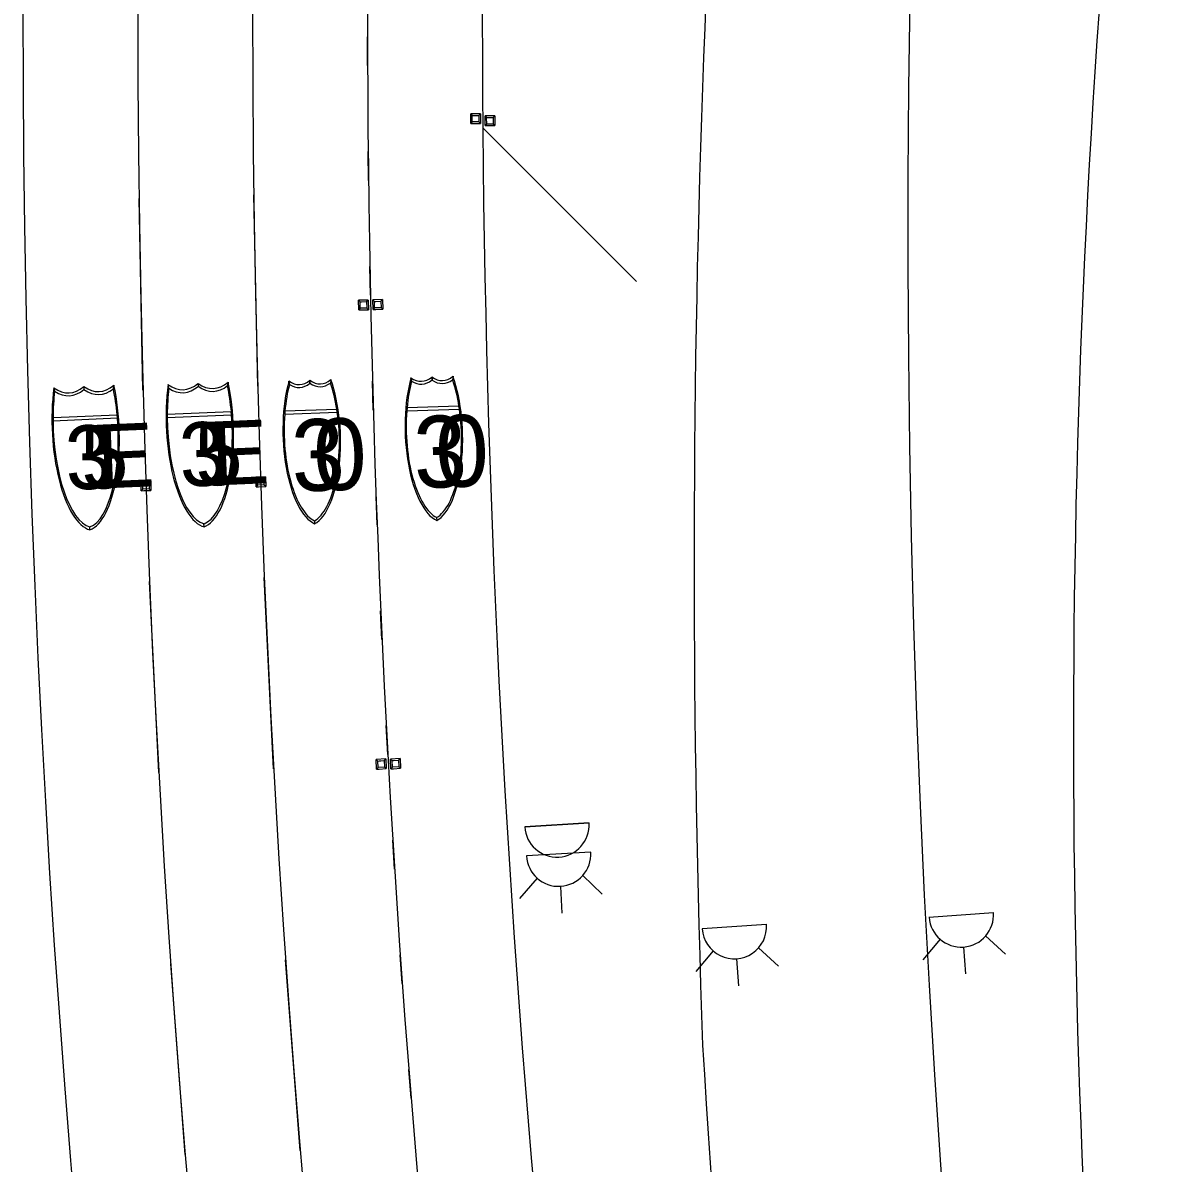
# Model space of a CAD drawing. Extents: x 2471014 to 2497726, y 6959577 to 6980268.
# Drawn here: x 2488424.4 to 2488544.1, y 6963415.2 to 6963534.3 of the extents above; entities that cross this region are included whole.
import ezdxf

# ---------------------------------------------------------------- set-up
doc = ezdxf.new("R2010")
doc.units = 0
for name, color, linetype in [('13', 7, 'Continuous'), ('18', 7, 'Continuous'), ('23', 7, 'Continuous'), ('59', 7, 'Continuous'), ('C-COMM-IDEN', 7, 'Continuous'), ('G-GRID-MAJR', 7, 'Continuous'), ('Level 30', 7, 'Continuous'), ('Level 40', 7, 'Continuous'), ('PMK_Del_D-SY_SZ_TYC_CTB', 7, 'Continuous'), ('PMK_Pav_Mark_Multi_Shield', 7, 'Continuous'), ('RDWY_PAVE_XSTREET_FOC', 7, 'Continuous'), ('V7_25', 7, 'Continuous')]:
    doc.layers.add(name, color=color, linetype=linetype)

msp = doc.modelspace()

# ---------------------------------------------------------------- linework, layer by layer
at = {"layer": '13'}
for centre, radius, start, end in [((2489874.44, 6963535.43), 1450, 149.83805, 187.72757), ((2489908.57, 6963477.79), 1414, 165.82987, 182.03801), ((2489609.21, 6963459.85), 1075, 166.29175, 188.37964), ((2489916.91, 6963512.7), 1424, 183.42984, 191.359)]:
    msp.add_arc(centre, radius, start, end, dxfattribs=at)
at = {"layer": '18'}
for centre, radius, start, end in [((2489916.91, 6963512.7), 1400, 142.23979, 191.359), ((2489874.44, 6963535.43), 1402, 167.63271, 187.72757)]:
    msp.add_arc(centre, radius, start, end, dxfattribs=at)
at = {"layer": '23'}
for p, q in [((2488471.24, 6963523.78), (2488471.23, 6963524.8)), ((2488472.24, 6963524.8), (2488471.23, 6963524.8)), ((2488471.23, 6963524.8), (2488471.39, 6963524.63)), ((2488472.07, 6963524.63), (2488472.24, 6963524.8)), ((2488472.24, 6963524.8), (2488472.25, 6963523.79)), ((2488471.4, 6963523.95), (2488471.24, 6963523.78)), ((2488471.24, 6963523.78), (2488471.51, 6963523.79)), ((2488471.39, 6963524.63), (2488471.53, 6963524.63)), ((2488472.07, 6963523.96), (2488471.4, 6963523.95)), ((2488471.51, 6963523.79), (2488472.25, 6963523.79)), ((2488471.53, 6963524.63), (2488472.07, 6963524.63)), ((2488472.25, 6963523.79), (2488472.07, 6963523.96)), ((2488473.74, 6963524.58), (2488472.73, 6963524.57)), ((2488472.74, 6963523.56), (2488472.73, 6963524.57)), ((2488472.73, 6963524.57), (2488472.89, 6963524.4)), ((2488472.9, 6963523.73), (2488472.74, 6963523.56)), ((2488472.89, 6963524.4), (2488473.03, 6963524.41)), ((2488473.57, 6963523.73), (2488472.9, 6963523.73)), ((2488473.03, 6963524.41), (2488473.57, 6963524.41)), ((2488473.57, 6963524.41), (2488473.74, 6963524.58)), ((2488473.75, 6963523.57), (2488473.57, 6963523.73)), ((2488473.74, 6963524.58), (2488473.75, 6963523.57)), ((2488472.74, 6963523.56), (2488473.01, 6963523.56)), ((2488473.01, 6963523.56), (2488473.75, 6963523.57)), ((2488460.52, 6963505.34), (2488459.51, 6963505.32)), ((2488459.53, 6963504.31), (2488459.51, 6963505.32)), ((2488459.51, 6963505.32), (2488459.67, 6963505.16)), ((2488459.69, 6963504.48), (2488459.53, 6963504.31)), ((2488459.67, 6963505.16), (2488459.81, 6963505.16)), ((2488460.36, 6963504.49), (2488459.69, 6963504.48)), ((2488459.81, 6963505.16), (2488460.35, 6963505.17)), ((2488460.35, 6963505.17), (2488460.52, 6963505.34)), ((2488460.55, 6963504.33), (2488460.36, 6963504.49)), ((2488460.52, 6963505.34), (2488460.55, 6963504.33)), ((2488462.02, 6963505.38), (2488461.01, 6963505.36)), ((2488461.03, 6963504.35), (2488461.01, 6963505.36)), ((2488461.01, 6963505.36), (2488461.17, 6963505.19)), ((2488461.19, 6963504.52), (2488461.03, 6963504.35)), ((2488461.17, 6963505.19), (2488461.31, 6963505.2)), ((2488461.86, 6963504.53), (2488461.19, 6963504.52)), ((2488461.31, 6963505.2), (2488461.85, 6963505.21)), ((2488461.85, 6963505.21), (2488462.02, 6963505.38)), ((2488462.04, 6963504.37), (2488461.86, 6963504.53)), ((2488462.02, 6963505.38), (2488462.04, 6963504.37)), ((2488459.53, 6963504.31), (2488459.8, 6963504.31)), ((2488459.8, 6963504.31), (2488460.55, 6963504.33)), ((2488461.03, 6963504.35), (2488461.3, 6963504.35)), ((2488461.3, 6963504.35), (2488462.04, 6963504.37)), ((2488449.78, 6963486.87), (2488448.77, 6963486.84)), ((2488448.8, 6963485.82), (2488448.77, 6963486.84)), ((2488448.77, 6963486.84), (2488448.93, 6963486.67)), ((2488448.93, 6963486.67), (2488449.07, 6963486.68)), ((2488449.07, 6963486.68), (2488449.61, 6963486.7)), ((2488449.61, 6963486.7), (2488449.78, 6963486.87)), ((2488449.78, 6963486.87), (2488449.82, 6963485.86)), ((2488437.79, 6963486.46), (2488436.77, 6963486.43)), ((2488436.81, 6963485.42), (2488436.77, 6963486.43)), ((2488436.77, 6963486.43), (2488436.94, 6963486.27)), ((2488436.96, 6963485.59), (2488436.81, 6963485.42)), ((2488436.81, 6963485.42), (2488437.08, 6963485.43)), ((2488436.94, 6963486.27), (2488437.08, 6963486.27)), ((2488437.64, 6963485.61), (2488436.96, 6963485.59)), ((2488437.08, 6963486.27), (2488437.62, 6963486.29)), ((2488437.08, 6963485.43), (2488437.82, 6963485.45)), ((2488437.62, 6963486.29), (2488437.79, 6963486.46)), ((2488437.82, 6963485.45), (2488437.64, 6963485.61)), ((2488437.79, 6963486.46), (2488437.82, 6963485.45)), ((2488448.96, 6963486), (2488448.8, 6963485.82)), ((2488448.8, 6963485.82), (2488449.07, 6963485.83)), ((2488449.63, 6963486.02), (2488448.96, 6963486)), ((2488449.07, 6963485.83), (2488449.82, 6963485.86)), ((2488449.82, 6963485.86), (2488449.63, 6963486.02)), ((2488462.36, 6963457.4), (2488461.34, 6963457.34)), ((2488461.4, 6963456.33), (2488461.34, 6963457.34)), ((2488461.34, 6963457.34), (2488461.51, 6963457.18)), ((2488461.51, 6963457.18), (2488461.65, 6963457.19)), ((2488461.65, 6963457.19), (2488462.19, 6963457.22)), ((2488462.19, 6963457.22), (2488462.36, 6963457.4)), ((2488462.36, 6963457.4), (2488462.41, 6963456.39)), ((2488463.86, 6963457.44), (2488462.85, 6963457.38)), ((2488462.9, 6963456.37), (2488462.85, 6963457.38)), ((2488462.85, 6963457.38), (2488463.01, 6963457.22)), ((2488463.01, 6963457.22), (2488463.16, 6963457.23)), ((2488463.73, 6963456.58), (2488463.05, 6963456.54)), ((2488463.16, 6963457.23), (2488463.69, 6963457.26)), ((2488463.69, 6963457.26), (2488463.86, 6963457.44)), ((2488463.91, 6963456.42), (2488463.73, 6963456.58)), ((2488463.86, 6963457.44), (2488463.91, 6963456.42)), ((2488461.55, 6963456.51), (2488461.4, 6963456.33)), ((2488461.4, 6963456.33), (2488461.67, 6963456.34)), ((2488462.23, 6963456.54), (2488461.55, 6963456.51)), ((2488461.67, 6963456.34), (2488462.41, 6963456.39)), ((2488462.41, 6963456.39), (2488462.23, 6963456.54)), ((2488463.05, 6963456.54), (2488462.9, 6963456.37)), ((2488462.9, 6963456.37), (2488463.17, 6963456.38)), ((2488463.17, 6963456.38), (2488463.91, 6963456.42))]:
    msp.add_line(p, q, dxfattribs=at)
for points in [[(2488471.4, 6963523.95), (2488471.39, 6963524.63), (2488472.07, 6963524.63), (2488472.07, 6963523.96)], [(2488472.9, 6963523.73), (2488472.89, 6963524.4), (2488473.57, 6963524.41), (2488473.57, 6963523.73)], [(2488459.69, 6963504.48), (2488459.67, 6963505.16), (2488460.35, 6963505.17), (2488460.36, 6963504.49)], [(2488461.19, 6963504.52), (2488461.17, 6963505.19), (2488461.85, 6963505.21), (2488461.86, 6963504.53)], [(2488448.96, 6963486), (2488448.93, 6963486.67), (2488449.61, 6963486.7), (2488449.63, 6963486.02)], [(2488436.96, 6963485.59), (2488436.94, 6963486.27), (2488437.62, 6963486.29), (2488437.64, 6963485.61)], [(2488461.55, 6963456.51), (2488461.51, 6963457.18), (2488462.19, 6963457.22), (2488462.23, 6963456.54)], [(2488463.05, 6963456.54), (2488463.01, 6963457.22), (2488463.69, 6963457.26), (2488463.73, 6963456.58)]]:
    msp.add_lwpolyline(points, close=True, dxfattribs=at)
at = {"layer": '59'}
msp.add_arc((2489874.44, 6963535.43), 1414, 167.6301, 187.72757, dxfattribs=at)
at = {"layer": 'C-COMM-IDEN'}
for p, q in [((2488476.88, 6963450.32), (2488483.61, 6963450.71)), ((2488483.61, 6963450.71), (2488476.88, 6963450.32)), ((2488483.79, 6963447.66), (2488477.05, 6963447.27)), ((2488478.17, 6963444.95), (2488476.33, 6963442.82)), ((2488482.94, 6963445.22), (2488484.96, 6963443.26)), ((2488480.61, 6963444.09), (2488480.77, 6963441.29))]:
    msp.add_line(p, q, dxfattribs=at)
for centre in [(2488480.24, 6963450.51), (2488480.42, 6963447.46)]:
    msp.add_arc(centre, 3.37, 183.2424, 3.2424, dxfattribs=at)
at = {"layer": 'G-GRID-MAJR'}
msp.add_line((2488472.49, 6963523.33), (2488488.54, 6963507.28), dxfattribs=at)
at = {"layer": 'Level 30'}
for p, q in [((2488519.12, 6963440.86), (2488525.85, 6963441.36)), ((2488525.04, 6963438.91), (2488527.1, 6963436.99)), ((2488520.28, 6963438.56), (2488518.47, 6963436.4)), ((2488522.73, 6963437.75), (2488522.94, 6963434.94))]:
    msp.add_line(p, q, dxfattribs=at)
msp.add_arc((2488522.49, 6963441.11), 3.37, 184.2283, 4.2282, dxfattribs=at)
at = {"layer": 'Level 40'}
for p, q in [((2488460.45, 6963529.84), (2488460.44, 6963532.84)), ((2488460.55, 6963517.84), (2488460.51, 6963520.84)), ((2488460.75, 6963505.84), (2488460.69, 6963508.84)), ((2488461.05, 6963493.85), (2488460.96, 6963496.85)), ((2488461.45, 6963481.86), (2488461.34, 6963484.85)), ((2488461.96, 6963469.87), (2488461.82, 6963472.86)), ((2488462.56, 6963457.88), (2488462.4, 6963460.88)), ((2488463.27, 6963445.9), (2488463.09, 6963448.9)), ((2488464.08, 6963433.93), (2488463.87, 6963436.92)), ((2488465, 6963421.96), (2488464.76, 6963424.96))]:
    msp.add_line(p, q, dxfattribs=at)
at = {"layer": 'PMK_Del_D-SY_SZ_TYC_CTB'}
for p, q in [((2488502.14, 6963440.12), (2488495.41, 6963439.65)), ((2488501.32, 6963437.67), (2488503.38, 6963435.75)), ((2488496.56, 6963437.34), (2488494.75, 6963435.19)), ((2488499.01, 6963436.52), (2488499.21, 6963433.71))]:
    msp.add_line(p, q, dxfattribs=at)
msp.add_arc((2488498.78, 6963439.89), 3.37, 184.033, 4.033, dxfattribs=at)
at = {"layer": 'PMK_Pav_Mark_Multi_Shield'}
for p, q in [((2488467.19, 6963497.3), (2488467.2, 6963496.99)), ((2488467.2, 6963496.99), (2488467.19, 6963497.3)), ((2488469.38, 6963497.37), (2488469.34, 6963497.01)), ((2488469.38, 6963497.37), (2488469.34, 6963497.01)), ((2488427.76, 6963495.81), (2488427.67, 6963496.18)), ((2488427.76, 6963495.81), (2488427.67, 6963496.18)), ((2488430.81, 6963496.31), (2488430.82, 6963496)), ((2488433.89, 6963496.07), (2488433.94, 6963496.44)), ((2488433.94, 6963496.44), (2488433.89, 6963496.07)), ((2488439.68, 6963496.13), (2488439.6, 6963496.5)), ((2488439.68, 6963496.13), (2488439.6, 6963496.5)), ((2488442.73, 6963496.63), (2488442.75, 6963496.32)), ((2488445.82, 6963496.39), (2488445.87, 6963496.77)), ((2488445.87, 6963496.77), (2488445.82, 6963496.39)), ((2488452.29, 6963496.52), (2488452.23, 6963496.88)), ((2488452.23, 6963496.88), (2488452.29, 6963496.52)), ((2488452.23, 6963496.88), (2488452.23, 6963496.88)), ((2488454.42, 6963496.95), (2488454.43, 6963496.64)), ((2488454.43, 6963496.64), (2488454.42, 6963496.95)), ((2488456.61, 6963497.02), (2488456.58, 6963496.66)), ((2488456.61, 6963497.02), (2488456.58, 6963496.66)), ((2488465.05, 6963496.87), (2488464.99, 6963497.23)), ((2488464.99, 6963497.23), (2488465.05, 6963496.87)), ((2488464.99, 6963497.23), (2488464.99, 6963497.23)), ((2488451.81, 6963493.74), (2488451.79, 6963493.42)), ((2488457.24, 6963493.92), (2488451.81, 6963493.74)), ((2488457.24, 6963493.92), (2488457.29, 6963493.61)), ((2488457.29, 6963493.61), (2488457.24, 6963493.92)), ((2488464.58, 6963494.09), (2488464.55, 6963493.77)), ((2488464.55, 6963493.77), (2488470.05, 6963493.95)), ((2488470, 6963494.27), (2488464.58, 6963494.09)), ((2488470, 6963494.27), (2488470.05, 6963493.95)), ((2488470.05, 6963493.95), (2488470, 6963494.27)), ((2488434.29, 6963493.33), (2488427.59, 6963493.05)), ((2488427.59, 6963493.05), (2488427.59, 6963492.73)), ((2488427.59, 6963492.73), (2488434.32, 6963493.02)), ((2488434.29, 6963493.33), (2488434.32, 6963493.02)), ((2488434.32, 6963493.02), (2488434.29, 6963493.33)), ((2488446.21, 6963493.65), (2488439.52, 6963493.37)), ((2488439.52, 6963493.37), (2488439.52, 6963493.06)), ((2488439.52, 6963493.06), (2488446.24, 6963493.34)), ((2488446.21, 6963493.65), (2488446.24, 6963493.34)), ((2488446.24, 6963493.34), (2488446.21, 6963493.65)), ((2488451.79, 6963493.42), (2488457.29, 6963493.61)), ((2488443.37, 6963481.65), (2488443.36, 6963481.96)), ((2488454.91, 6963482.27), (2488454.92, 6963481.96)), ((2488467.67, 6963482.62), (2488467.68, 6963482.31)), ((2488431.44, 6963481.32), (2488431.43, 6963481.64))]:
    msp.add_line(p, q, dxfattribs=at)
for centre, major_axis, ratio, start_param, end_param in [((2488465.79, 6963506.22), (-0.31, 9.37), 0.400296, 2.845044, 3.438144), ((2488467.98, 6963506.3), (-0.31, 9.37), 0.400296, 2.845044, 3.438144), ((2488466.63, 6963491.46), (-0.31, 9.37), 0.400296, 3.342954, 5.381394), ((2488431.46, 6963491.89), (-0.45, 10.62), 0.373432, 1.138774, 3.023674), ((2488428.63, 6963510.63), (-0.64, 14.99), 0.373432, 2.857844, 3.425344), ((2488431.76, 6963510.77), (-0.64, 14.99), 0.373432, 2.857844, 3.425344), ((2488431.77, 6963510.77), (-0.65, 15.3), 0.373432, 2.862234, 3.405964), ((2488430.53, 6963491.85), (-0.45, 10.62), 0.373432, 3.259514, 5.144414), ((2488430.53, 6963491.85), (-0.44, 10.3), 0.373432, 4.841111, 5.118585), ((2488443.39, 6963492.21), (-0.45, 10.62), 0.373432, 1.138774, 3.023674), ((2488443.39, 6963492.21), (-0.44, 10.3), 0.373432, 1.164604, 1.442074), ((2488440.55, 6963510.96), (-0.64, 14.99), 0.373432, 2.857844, 3.425344), ((2488440.55, 6963510.96), (-0.65, 15.3), 0.373432, 2.877224, 3.420954), ((2488443.69, 6963511.09), (-0.64, 14.99), 0.373432, 2.857844, 3.425344), ((2488443.7, 6963511.1), (-0.65, 15.3), 0.373432, 2.862234, 3.405964), ((2488442.46, 6963492.17), (-0.45, 10.62), 0.373432, 3.259514, 5.144414), ((2488442.46, 6963492.17), (-0.44, 10.3), 0.373432, 4.841111, 5.118585), ((2488455.37, 6963491.16), (-0.31, 9.37), 0.400296, 0.901794, 2.940234), ((2488455.37, 6963491.16), (-0.3, 9.06), 0.400296, 0.924954, 1.269494), ((2488453.03, 6963505.88), (-0.31, 9.37), 0.400296, 2.845044, 3.438144), ((2488453.02, 6963505.88), (-0.32, 9.68), 0.400296, 2.870004, 3.430874), ((2488455.22, 6963505.95), (-0.31, 9.37), 0.400296, 2.845044, 3.438144), ((2488455.23, 6963505.96), (-0.32, 9.68), 0.400296, 2.852314, 3.413184), ((2488453.87, 6963491.12), (-0.31, 9.37), 0.400296, 3.342954, 5.381394), ((2488453.87, 6963491.12), (-0.3, 9.06), 0.400296, 5.01369, 5.358233), ((2488468.13, 6963491.51), (-0.31, 9.37), 0.400296, 0.901794, 2.940234), ((2488468.13, 6963491.51), (-0.3, 9.06), 0.400296, 0.924954, 1.269494), ((2488465.78, 6963506.23), (-0.32, 9.68), 0.400296, 2.870004, 3.430874), ((2488467.99, 6963506.3), (-0.32, 9.68), 0.400296, 2.852314, 3.413184), ((2488466.63, 6963491.46), (-0.3, 9.06), 0.400296, 5.01369, 5.358233), ((2488431.46, 6963491.89), (-0.44, 10.3), 0.373432, 1.164604, 1.442074), ((2488428.62, 6963510.64), (-0.65, 15.3), 0.373432, 2.877224, 3.420954), ((2488468.13, 6963491.51), (-0.3, 9.06), 0.400296, 1.304694, 2.933384), ((2488466.63, 6963491.46), (-0.3, 9.06), 0.400296, 3.349804, 4.978494), ((2488431.46, 6963491.88), (-0.44, 10.3), 0.373432, 1.472354, 3.020104), ((2488430.53, 6963491.84), (-0.44, 10.3), 0.373432, 3.263084, 4.810824), ((2488443.39, 6963492.21), (-0.44, 10.3), 0.373432, 1.472354, 3.020104), ((2488442.46, 6963492.17), (-0.44, 10.3), 0.373432, 3.263084, 4.810824), ((2488455.37, 6963491.16), (-0.3, 9.06), 0.400296, 1.304694, 2.933384), ((2488453.87, 6963491.11), (-0.3, 9.06), 0.400296, 3.349804, 4.978494)]:
    msp.add_ellipse(centre, major_axis=major_axis, ratio=ratio, start_param=start_param, end_param=end_param, dxfattribs=at)
at = {"layer": 'RDWY_PAVE_XSTREET_FOC'}
for p, q in [((2488436.98, 6963495.94), (2488436.57, 6963515.93)), ((2488448.97, 6963496.34), (2488448.56, 6963516.34)), ((2488438.63, 6963455.97), (2488437.67, 6963475.95)), ((2488450.63, 6963456.38), (2488449.66, 6963476.35)), ((2488453.41, 6963416.48), (2488451.88, 6963436.42)), ((2488441.4, 6963416.07), (2488439.88, 6963436.01))]:
    msp.add_line(p, q, dxfattribs=at)
at = {"layer": 'V7_25'}
for radius in [1438, 1426]:
    msp.add_arc((2489874.44, 6963535.43), radius, 149.83805, 187.72757, dxfattribs=at)

# ---------------------------------------------------------------- texts
at = {"layer": 'PMK_Pav_Mark_Multi_Shield'}
for s, height, rotation, p in [('E', 6.67, 2.433, (2488432.31, 6963485.64)), ('3', 6.67, 2.433, (2488440.9, 6963485.82)), ('5', 6.67, 2.433, (2488442.52, 6963485.89)), ('E', 6.67, 2.433, (2488444.23, 6963485.96)), ('3', 7.5, 1.9036, (2488452.6, 6963485.32)), ('0', 7.5, 1.9036, (2488454.9, 6963485.4)), ('3', 7.5, 1.9036, (2488465.37, 6963485.67)), ('0', 7.5, 1.9036, (2488467.66, 6963485.75)), ('3', 6.67, 2.433, (2488428.98, 6963485.49)), ('5', 6.67, 2.433, (2488430.6, 6963485.56))]:
    msp.add_text(s, height=height, rotation=rotation, dxfattribs=at).set_placement(p)

doc.saveas('drawing.dxf')
